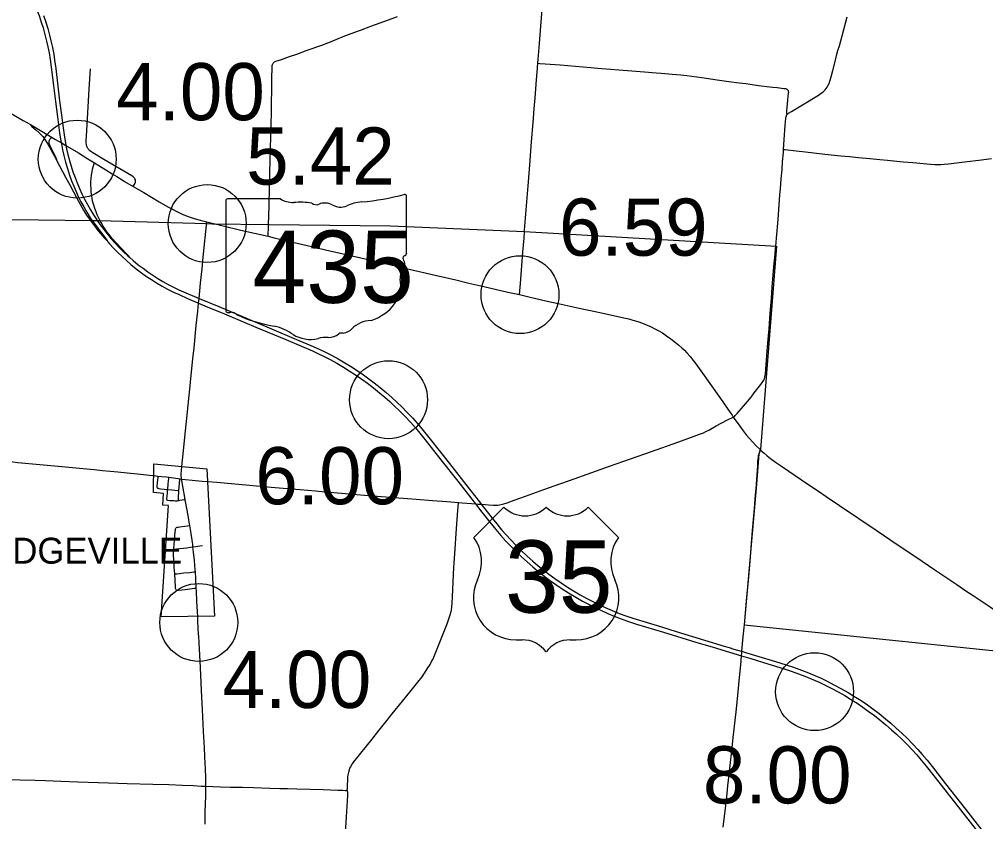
# Model space of a CAD drawing. Extents: x 1597222 to 1925846, y 496284 to 911751.
# Drawn here: x 1658757 to 1677369, y 576766 to 592215 of the extents above; entities that cross this region are included whole.
import ezdxf

# ---------------------------------------------------------------- set-up
doc = ezdxf.new("R2010")
doc.units = 0
for name, color, linetype in [('Default', 7, 'Continuous'), ('GM_X_City_Street', 7, 'Continuous'), ('GM_X_Corporation', 7, 'Continuous'), ('GM_X_Corporation_Text', 7, 'Continuous'), ('GM_X_County_Road', 7, 'Continuous'), ('GM_X_Interchange_Ramps', 7, 'Continuous'), ('GM_X_State_Route', 7, 'Continuous'), ('GM_X_State_Shield', 7, 'Continuous'), ('GM_X_Township', 7, 'Continuous'), ('GM_X_Township_Road', 7, 'Continuous'), ('GM_X_US_Route', 7, 'Continuous'), ('GM_X_US_Shield', 7, 'Continuous')]:
    doc.layers.add(name, color=color, linetype=linetype)

msp = doc.modelspace()

# ---------------------------------------------------------------- linework, layer by layer
at = {"layer": 'Default'}
for centre in [(1659873, 589523), (1659873, 589523), (1662376, 588283), (1662376, 588283), (1668401, 586914), (1668401, 586914), (1665868, 584891), (1665868, 584891), (1662214, 580602), (1662214, 580602), (1674074, 579269)]:
    msp.add_circle(centre, 750, dxfattribs=at)
at = {"layer": 'GM_X_City_Street'}
for points in [[(1661351, 583429), (1661427, 583421)], [(1661427, 583421), (1661424, 583393), (1661414, 583296), (1661405, 583215), (1661407, 583207), (1661409, 583200), (1661414, 583193), (1661420, 583189), (1661430, 583185), (1661441, 583182), (1661475, 583177), (1661548, 583171), (1661616, 583164)], [(1661427, 583421), (1661496, 583414), (1661592, 583405), (1661635, 583399)], [(1661616, 583164), (1661626, 583271), (1661634, 583373), (1661635, 583399)], [(1661635, 583399), (1661769, 583383), (1661817, 583376), (1661848, 583370)], [(1661832, 583144), (1661847, 583350), (1661848, 583370)], [(1661848, 583370), (1661883, 583364)], [(1661883, 583364), (1661953, 583356), (1662084, 583342), (1662281, 583325), (1662385, 583316)], [(1661820, 582944), (1661804, 582942), (1661794, 582940), (1661780, 582939), (1661760, 582939), (1661732, 582941), (1661698, 582944), (1661657, 582947), (1661614, 582952), (1661610, 582954), (1661607, 582956), (1661604, 582959), (1661602, 582962), (1661600, 582967), (1661599, 582970), (1661598, 582975), (1661598, 582978), (1661604, 583040), (1661609, 583092), (1661614, 583141), (1661616, 583164)], [(1661616, 583164), (1661694, 583156), (1661807, 583146), (1661832, 583144)], [(1661820, 582944), (1661820, 582960), (1661821, 582970), (1661824, 583016), (1661831, 583124), (1661832, 583144)], [(1661952, 582965), (1661926, 582961), (1661893, 582956), (1661845, 582948), (1661820, 582944)], [(1661732, 582013), (1661733, 582027), (1661752, 582256), (1661754, 582288), (1661764, 582386), (1661768, 582402), (1661774, 582417), (1661785, 582429), (1661800, 582436), (1661816, 582439), (1661849, 582443), (1661946, 582456), (1661995, 582463), (1662041, 582470)], [(1661750, 581536), (1661740, 581667), (1661731, 581814), (1661726, 581896), (1661727, 581945), (1661731, 581994), (1661732, 582013)], [(1661732, 582013), (1661783, 582018), (1661984, 582041), (1662056, 582049), (1662102, 582056)], [(1662102, 582056), (1662156, 582064), (1662237, 582075), (1662286, 582081)], [(1661750, 581536), (1661780, 581539), (1661796, 581540), (1661925, 581555), (1662039, 581567), (1662119, 581575), (1662149, 581579)], [(1662165, 581257), (1662133, 581253), (1661954, 581233), (1661889, 581226), (1661824, 581218), (1661807, 581217), (1661791, 581220), (1661777, 581228), (1661769, 581242), (1661765, 581258), (1661763, 581291), (1661750, 581536)]]:
    msp.add_lwpolyline(points, dxfattribs=at)
at = {"layer": 'GM_X_Corporation'}
msp.add_lwpolyline([(1661348, 583658), (1662369, 583561), (1662517, 580722), (1661488, 580713), (1661631, 582852), (1661519, 582859), (1661531, 583087), (1661343, 583102)], close=True, dxfattribs=at)
at = {"layer": 'GM_X_County_Road'}
for points in [[(1673543, 590381), (1673551, 590389), (1673561, 590398), (1673574, 590408), (1673631, 590442), (1673841, 590569), (1674149, 590757), (1674204, 590793), (1674230, 590812), (1674254, 590834), (1674277, 590857), (1674297, 590882), (1674315, 590909), (1674331, 590937), (1674352, 590981), (1674369, 591027), (1674391, 591105), (1674424, 591232), (1674481, 591455), (1674498, 591518), (1674525, 591613), (1674552, 591707), (1674605, 591897), (1674704, 592261)], [(1673477, 589710), (1673491, 589899), (1673503, 590079), (1673510, 590177), (1673515, 590242), (1673520, 590308), (1673521, 590325), (1673525, 590341), (1673530, 590358), (1673535, 590369), (1673543, 590381)], [(1673326, 587848), (1673339, 588003), (1673370, 588363), (1673391, 588641), (1673407, 588837), (1673417, 588951), (1673433, 589147), (1673447, 589327), (1673459, 589474), (1673473, 589654), (1673477, 589710)], [(1673477, 589710), (1673508, 589707), (1673718, 589682), (1673897, 589662), (1674272, 589620), (1674582, 589588), (1674663, 589579), (1674744, 589572), (1674923, 589555), (1675135, 589535), (1675331, 589518), (1675478, 589504), (1675657, 589486), (1675787, 589473), (1675967, 589457), (1676309, 589426), (1676391, 589419), (1676440, 589418), (1676506, 589420), (1676572, 589424), (1676653, 589433), (1677011, 589478), (1677239, 589505), (1677483, 589534)], [(1673117, 585324), (1673123, 585356), (1673127, 585388), (1673148, 585650), (1673163, 585830), (1673187, 586124), (1673198, 586254), (1673206, 586352), (1673215, 586467), (1673226, 586630), (1673242, 586843), (1673260, 587055), (1673292, 587448), (1673314, 587693), (1673323, 587811), (1673326, 587848)], [(1668393, 586915), (1668573, 586871), (1668925, 586789), (1669133, 586744), (1669598, 586644), (1669759, 586610), (1670031, 586550), (1670400, 586469), (1670495, 586446), (1670574, 586424), (1670668, 586395), (1670760, 586362), (1670852, 586326), (1670927, 586294), (1671000, 586258), (1671072, 586218), (1671142, 586176), (1671224, 586121), (1671304, 586064), (1671395, 585995), (1671458, 585943), (1671519, 585888), (1671566, 585842), (1671611, 585795), (1671676, 585721), (1671738, 585646), (1671788, 585581), (1671884, 585448), (1672054, 585206), (1672262, 584912), (1672450, 584642), (1672486, 584592), (1672509, 584558)], [(1672509, 584558), (1672530, 584571), (1672546, 584585), (1672585, 584625), (1672706, 584765), (1672783, 584858), (1672851, 584942), (1672913, 585023), (1672990, 585123), (1673036, 585182), (1673066, 585221), (1673086, 585251), (1673094, 585265), (1673108, 585294), (1673117, 585324)], [(1667214, 582912), (1667286, 582907), (1667465, 582892), (1667542, 582886), (1667597, 582882), (1667655, 582878), (1667727, 582872), (1667792, 582867), (1667891, 582862), (1667941, 582861), (1667974, 582862), (1668007, 582866), (1668039, 582872), (1668087, 582885), (1668150, 582905), (1668289, 582954), (1668505, 583033), (1668860, 583159), (1669169, 583269), (1669354, 583335), (1669787, 583489), (1670127, 583609), (1670529, 583750), (1670931, 583893), (1671441, 584074), (1671703, 584170), (1671857, 584226), (1671933, 584256), (1671978, 584277), (1672037, 584307), (1672181, 584385), (1672398, 584501), (1672509, 584558)], [(1672509, 584558), (1672541, 584513), (1672601, 584428), (1672698, 584295), (1672758, 584217), (1672821, 584142), (1672876, 584080), (1672945, 584009), (1673027, 583930), (1673029, 583928)], [(1656846, 583945), (1656933, 583938), (1657439, 583898), (1657717, 583874), (1657814, 583863), (1657895, 583851), (1657992, 583831), (1658264, 583770), (1658472, 583725), (1658552, 583710), (1658633, 583697), (1658731, 583685), (1659579, 583605), (1659987, 583565), (1660199, 583545), (1660362, 583530), (1660656, 583500), (1660835, 583483), (1661031, 583462), (1661324, 583432), (1661351, 583429)], [(1672802, 581413), (1672814, 581553), (1672832, 581782), (1672845, 581946), (1672859, 582126), (1672879, 582371), (1672916, 582796), (1672938, 583057), (1672948, 583172), (1672962, 583351), (1672974, 583534), (1672979, 583616), (1672983, 583699), (1672986, 583746), (1672991, 583782), (1672997, 583815), (1673006, 583851), (1673018, 583890), (1673029, 583928)], [(1673029, 583928), (1673100, 583863), (1673163, 583810), (1673227, 583759), (1673320, 583691), (1673454, 583596), (1673943, 583265), (1674148, 583129), (1674297, 583028), (1674556, 582853), (1675277, 582368), (1675684, 582092), (1676024, 581863), (1676392, 581615), (1676813, 581331), (1676990, 581211), (1677126, 581120), (1677453, 580900), (1677630, 580782), (1677766, 580690), (1678105, 580460), (1678419, 580251), (1678704, 580058), (1678915, 579914)], [(1662385, 583316), (1662559, 583301)], [(1662559, 583301), (1662908, 583271), (1663610, 583209), (1663839, 583189), (1664165, 583159), (1664459, 583134), (1664639, 583119), (1664739, 583110), (1664883, 583097), (1665112, 583076), (1665406, 583051), (1665815, 583018), (1666403, 582973), (1666714, 582949), (1666992, 582929), (1667214, 582912)], [(1672722, 580557), (1672772, 581096), (1672795, 581341), (1672802, 581413)], [(1672315, 576658), (1672326, 576772), (1672350, 576968), (1672381, 577245), (1672403, 577457), (1672433, 577734), (1672460, 577962), (1672478, 578125), (1672507, 578386), (1672544, 578712), (1672569, 578941), (1672596, 579202), (1672629, 579544), (1672651, 579789), (1672667, 579959), (1672672, 580018), (1672675, 580047), (1672695, 580263), (1672718, 580508), (1672722, 580557)], [(1658375, 577587), (1658769, 577573), (1659064, 577564), (1659261, 577557), (1659556, 577547), (1659884, 577536), (1660474, 577516), (1660835, 577504), (1661327, 577488), (1661638, 577479), (1661900, 577469), (1662114, 577461), (1662261, 577453), (1662338, 577448), (1662351, 577447)], [(1662351, 577447), (1662482, 577444), (1662629, 577439), (1662826, 577433), (1663055, 577428), (1663268, 577422), (1663580, 577413), (1663777, 577406), (1663924, 577403), (1664104, 577399), (1664612, 577384), (1664892, 577374), (1664990, 577371), (1665034, 577368), (1665073, 577366)], [(1665073, 577366), (1665075, 577330), (1665077, 577306), (1665079, 577273), (1665054, 576858), (1665019, 576335)]]:
    msp.add_lwpolyline(points, dxfattribs=at)
at = {"layer": 'GM_X_Interchange_Ramps'}
for points in [[(1658970, 590188), (1658980, 590172), (1658987, 590162), (1658996, 590150), (1659041, 590115), (1659077, 590086), (1659139, 590030), (1659174, 589995), (1659207, 589958), (1659237, 589920), (1659274, 589866), (1659309, 589810), (1659364, 589710), (1659472, 589508), (1659476, 589501), (1659649, 589176), (1659735, 589018), (1659865, 588772), (1659928, 588657), (1659994, 588544), (1660054, 588447), (1660109, 588366), (1660126, 588343), (1660140, 588325), (1660203, 588239), (1660271, 588150), (1660358, 588049), (1660400, 588000), (1660417, 587983), (1660435, 587966), (1660447, 587956)], [(1659392, 589942), (1659373, 589928), (1659359, 589919), (1659347, 589908), (1659337, 589895), (1659329, 589881), (1659325, 589865), (1659324, 589849), (1659327, 589833), (1659332, 589817), (1659345, 589788), (1659463, 589548), (1659476, 589518), (1659477, 589510), (1659476, 589501)], [(1660883, 587631), (1660882, 587634), (1660879, 587638), (1660857, 587663), (1660820, 587702), (1660623, 587910), (1660547, 587996), (1660485, 588072), (1660445, 588124), (1660408, 588177), (1660373, 588233), (1660333, 588304), (1660314, 588338), (1660294, 588376), (1660259, 588450), (1660234, 588510), (1660211, 588572), (1660192, 588634), (1660175, 588697), (1660161, 588761), (1660151, 588826), (1660143, 588890), (1660138, 588956), (1660136, 589021), (1660137, 589086), (1660141, 589152), (1660148, 589217), (1660159, 589281), (1660169, 589329), (1660181, 589377), (1660186, 589392), (1660206, 589452)]]:
    msp.add_lwpolyline(points, dxfattribs=at)
at = {"layer": 'GM_X_State_Route'}
for points in [[(1668393, 586915), (1668411, 587126), (1668458, 587731), (1668478, 587999), (1668488, 588129), (1668490, 588156), (1668508, 588385), (1668521, 588548), (1668537, 588777), (1668562, 589088), (1668587, 589415), (1668622, 589856), (1668652, 590232), (1668674, 590494), (1668690, 590706), (1668716, 591050), (1668728, 591197), (1668742, 591371), (1668748, 591442), (1668774, 591753), (1668794, 591998), (1668841, 592570)], [(1658299, 590586), (1658313, 590577), (1658500, 590462), (1658646, 590376), (1658832, 590268), (1658970, 590188)], [(1658970, 590188), (1659231, 590037), (1659392, 589942), (1659457, 589903), (1659501, 589877)], [(1659501, 589877), (1659563, 589841), (1659656, 589785), (1659683, 589769), (1659896, 589643), (1660078, 589531), (1660206, 589452)], [(1660206, 589452), (1660287, 589402), (1660421, 589317), (1660547, 589239), (1660635, 589186), (1660755, 589113)], [(1660755, 589113), (1660786, 589094), (1660950, 588998), (1661153, 588878), (1661449, 588703), (1661619, 588604), (1661706, 588557), (1661794, 588513), (1661883, 588473), (1661989, 588428), (1662066, 588399), (1662144, 588374), (1662239, 588346), (1662370, 588315)], [(1662203, 586676), (1662211, 586752), (1662220, 586842), (1662249, 587133), (1662277, 587410), (1662300, 587639), (1662370, 588315)], [(1662370, 588315), (1662657, 588245), (1663024, 588158), (1663551, 588037), (1663664, 588011), (1663967, 587939), (1664382, 587843), (1664654, 587779), (1665532, 587576), (1666267, 587405), (1666682, 587309), (1667162, 587198), (1667417, 587138), (1667705, 587072), (1668168, 586964), (1668393, 586915)], [(1662062, 585299), (1662100, 585681), (1662122, 585893), (1662165, 586317), (1662194, 586594), (1662203, 586676)], [(1661890, 583607), (1661915, 583852), (1661960, 584293), (1661984, 584538), (1662010, 584783), (1662055, 585223), (1662062, 585299)], [(1662167, 581215), (1662165, 581257), (1662156, 581450), (1662149, 581579), (1662147, 581614), (1662131, 581793), (1662114, 581957), (1662102, 582056), (1662097, 582103), (1662065, 582314), (1662041, 582470), (1662038, 582493), (1662016, 582622), (1661989, 582767), (1661952, 582965), (1661943, 583009), (1661913, 583187), (1661887, 583333), (1661883, 583364), (1661880, 583382), (1661877, 583432), (1661877, 583465), (1661881, 583531), (1661890, 583607)], [(1662193, 580718), (1662177, 581007), (1662167, 581204), (1662167, 581215)], [(1662197, 580629), (1662193, 580718)], [(1662335, 576718), (1662339, 576964), (1662347, 577259), (1662351, 577423), (1662351, 577447), (1662352, 577488), (1662349, 577619), (1662342, 577783), (1662330, 578012), (1662321, 578192), (1662306, 578504), (1662284, 578929), (1662265, 579290), (1662244, 579732), (1662220, 580207), (1662213, 580338), (1662211, 580371), (1662197, 580629)]]:
    msp.add_lwpolyline(points, dxfattribs=at)
at = {"layer": 'GM_X_State_Shield'}
for p, q in [((1662734, 588720), (1662734, 586607)), ((1663787, 588757), (1662768, 588757)), ((1666214, 587703), (1666214, 588809)), ((1666214, 587704), (1666214, 587703))]:
    msp.add_line(p, q, dxfattribs=at)
for centre, major_axis, start_param, end_param in [((1662774, 588725), (40.3, 0), 1.712693, 3.28349), ((1664030, 589002), (391, 0), 4.042523, 4.731795), ((1665445, 588111), (743, 0), 1.699011, 2.107814), ((1664974, 591638), (3691, 0), 4.814394, 5.042369), ((1666176, 588814), (38.7, 0), 6.141152, 7.989035), ((1664160, 587570), (1404, 0), 1.404758, 1.657858), ((1664478, 588736), (113, 0), 3.836095, 5.185415), ((1664644, 588491), (235, 0), 0.950623, 2.079405), ((1664947, 588826), (282, 0), 4.081561, 5.145723), ((1666205, 587622), (60, 0), 1.883978, 3.671073), ((1665824, 587483), (360, 0), 5.934695, 6.695948), ((1666173, 587699), (41.5, 0), 5.05454, 6.418171), ((1665181, 587100), (923, 0), 5.101752, 6.440018), ((1666353, 587241), (262, 0), 2.387724, 3.262537), ((1662774, 586602), (40.7, 0), 3.00124, 4.508301), ((1662780, 586819), (310, 0), 4.665946, 4.897461), ((1662844, 586485), (112, 0), 0.519207, 1.627899), ((1664257, 588384), (2665, 0), 4.195997, 4.488961), ((1663462, 585658), (834, 0), 0.823519, 1.323587), ((1665570, 586014), (506, 0), 1.647645, 2.488434), ((1664364, 586475), (529, 0), 4.026481, 4.996735), ((1664670, 585744), (435, 0), 1.495662, 1.94098), ((1664709, 586316), (282, 0), 4.691044, 5.507374), ((1664964, 586112), (79.4, 0), 1.147584, 2.315152), ((1664930, 586402), (298, 0), 4.937069, 5.64225)]:
    msp.add_ellipse(centre, major_axis=major_axis, ratio=0.8, start_param=start_param, end_param=end_param, dxfattribs=at)
at = {"layer": 'GM_X_Township'}
msp.add_lwpolyline([(1640772, 591419), (1641501, 591232), (1645959, 590087), (1646099, 590051), (1651332, 588679), (1652031, 588630), (1654972, 588478), (1658610, 588362), (1660153, 588344), (1660296, 588340), (1662371, 588281), (1662472, 588280), (1663570, 588267), (1665903, 588241), (1668490, 588131), (1673343, 587846), (1673034, 583935), (1673000, 583850), (1672955, 583266), (1672719, 580558), (1678923, 579915)], dxfattribs=at)
at = {"layer": 'GM_X_Township_Road'}
for points in [[(1663558, 588266), (1663564, 588427), (1663569, 588640), (1663578, 588967), (1663585, 589279), (1663590, 589476), (1663597, 589722), (1663602, 589968), (1663607, 590214), (1663611, 590394), (1663616, 590623), (1663619, 590837), (1663623, 591083), (1663624, 591279), (1663626, 591312), (1663628, 591329), (1663631, 591345), (1663637, 591360), (1663645, 591374), (1663656, 591385), (1663669, 591394), (1663683, 591402), (1663699, 591408), (1663808, 591445), (1663963, 591499), (1664102, 591547), (1664303, 591619), (1664581, 591719), (1664719, 591772), (1664871, 591833), (1664993, 591882), (1665146, 591940), (1665330, 592009), (1665530, 592083), (1665869, 592206), (1666039, 592267)], [(1668742, 591371), (1668784, 591368), (1668882, 591360), (1669176, 591338), (1669618, 591300), (1669765, 591288), (1669896, 591278), (1670059, 591264), (1670386, 591238), (1670795, 591204), (1671024, 591185), (1671122, 591178), (1671334, 591159), (1671498, 591145), (1671612, 591134), (1671710, 591122), (1671905, 591094), (1672197, 591051), (1672424, 591020), (1672619, 590993), (1672750, 590977), (1672993, 590944), (1673156, 590924), (1673270, 590911), (1673352, 590902), (1673483, 590886), (1673499, 590884), (1673515, 590881), (1673524, 590878), (1673532, 590876), (1673539, 590873), (1673547, 590867), (1673554, 590861), (1673559, 590855), (1673563, 590847), (1673566, 590839), (1673568, 590831), (1673569, 590821), (1673569, 590809), (1673567, 590794), (1673562, 590739), (1673555, 590657), (1673535, 590444), (1673534, 590411), (1673535, 590399), (1673538, 590391), (1673543, 590381)], [(1660950, 588998), (1660969, 589031), (1660986, 589060), (1660992, 589076), (1660995, 589093), (1660995, 589110), (1660992, 589127), (1660985, 589144), (1660976, 589158), (1660965, 589170), (1660952, 589182), (1660924, 589201), (1660385, 589517), (1660173, 589643), (1660132, 589670), (1660108, 589691), (1660097, 589702), (1660087, 589715), (1660078, 589728), (1660070, 589742), (1660063, 589756), (1660057, 589771), (1660053, 589787), (1660049, 589802), (1660046, 589835), (1660046, 589883), (1660050, 589965), (1660102, 590868), (1660127, 591262)], [(1663551, 588037), (1663552, 588082), (1663556, 588190), (1663558, 588266)], [(1665073, 577366), (1665074, 577384), (1665076, 577407), (1665077, 577427), (1665078, 577457), (1665083, 577570), (1665086, 577620), (1665092, 577668), (1665101, 577717), (1665115, 577764), (1665126, 577795), (1665139, 577825), (1665155, 577853), (1665173, 577881), (1665202, 577921), (1665551, 578355), (1665663, 578496), (1665815, 578690), (1665938, 578843), (1666135, 579084), (1666279, 579263), (1666433, 579455), (1666513, 579558), (1666561, 579625), (1666615, 579707), (1666667, 579791), (1666698, 579848), (1666719, 579892), (1666751, 579968), (1666893, 580317), (1666995, 580576), (1667029, 580669), (1667055, 580747), (1667073, 580810), (1667079, 580836), (1667083, 580858), (1667087, 580882), (1667090, 580906), (1667095, 580972), (1667101, 581103), (1667128, 581659), (1667143, 581921), (1667178, 582411), (1667204, 582755), (1667214, 582905), (1667214, 582912)]]:
    msp.add_lwpolyline(points, dxfattribs=at)
at = {"layer": 'GM_X_US_Route'}
for points in [[(1658732, 593127), (1658799, 593014), (1658863, 592900), (1658917, 592798), (1658953, 592724), (1658995, 592635), (1659041, 592530), (1659091, 592408), (1659138, 592286), (1659181, 592161), (1659215, 592052), (1659250, 591925), (1659282, 591798), (1659307, 591686), (1659330, 591573), (1659351, 591443), (1659372, 591297), (1659417, 590939), (1659456, 590630), (1659493, 590337), (1659533, 590028), (1659545, 589947), (1659556, 589879)], [(1659225, 592286), (1659266, 592162), (1659305, 592037), (1659340, 591910), (1659367, 591799), (1659395, 591671), (1659419, 591542), (1659437, 591429), (1659459, 591266), (1659533, 590648), (1659569, 590371), (1659602, 590127), (1659627, 589948), (1659646, 589835), (1659656, 589785), (1659668, 589722), (1659694, 589610), (1659723, 589499), (1659755, 589389), (1659791, 589279), (1659830, 589171), (1659871, 589064), (1659916, 588958), (1659964, 588854), (1660015, 588750), (1660069, 588649), (1660126, 588549), (1660186, 588451), (1660249, 588355), (1660259, 588340), (1660315, 588261), (1660383, 588168), (1660454, 588078), (1660528, 587990), (1660604, 587904), (1660683, 587820), (1660764, 587739), (1660849, 587661), (1660883, 587631), (1660948, 587574), (1661049, 587491), (1661140, 587421), (1661233, 587353), (1661328, 587289), (1661426, 587227), (1661524, 587168), (1661625, 587112), (1661727, 587060), (1661831, 587010), (1661966, 586950), (1662177, 586860), (1662220, 586842), (1662601, 586683), (1663568, 586276), (1664143, 586034), (1664369, 585937), (1664533, 585863), (1664651, 585806), (1664768, 585746), (1664898, 585676), (1665025, 585602), (1665137, 585534), (1665261, 585454), (1665383, 585371), (1665489, 585294), (1665594, 585215), (1665710, 585124), (1665823, 585030), (1665934, 584933), (1666031, 584844), (1666125, 584753), (1666229, 584648), (1666330, 584540), (1666417, 584442), (1666512, 584330), (1666646, 584164), (1666869, 583881), (1667041, 583661), (1667354, 583260), (1667618, 582925), (1667655, 582878), (1667840, 582641), (1667953, 582500), (1668047, 582386), (1668133, 582287), (1668221, 582190), (1668313, 582095), (1668417, 581991), (1668537, 581878), (1668647, 581780), (1668747, 581695), (1668837, 581623), (1668954, 581533), (1669073, 581446), (1669194, 581362), (1669318, 581281), (1669430, 581212), (1669557, 581137), (1669686, 581065), (1669803, 581004), (1669920, 580946), (1670040, 580891), (1670175, 580832), (1670312, 580777), (1670436, 580732), (1670575, 580684), (1670763, 580624), (1671124, 580515), (1671407, 580429), (1671956, 580263), (1672332, 580145), (1672426, 580117), (1672521, 580090), (1672663, 580050), (1672675, 580047), (1672741, 580026), (1673321, 579850), (1673525, 579787), (1673665, 579740), (1673819, 579685), (1673957, 579631), (1674078, 579581), (1674198, 579528), (1674316, 579471), (1674447, 579404), (1674592, 579327), (1674720, 579254), (1674832, 579185), (1674970, 579097), (1675092, 579014), (1675198, 578937), (1675315, 578848), (1675443, 578746), (1675544, 578662), (1675642, 578575), (1675763, 578464), (1675857, 578372), (1675960, 578267), (1676060, 578159), (1676147, 578061), (1676242, 577948), (1676366, 577795), (1676598, 577497), (1676981, 577006), (1677293, 576604)], [(1659556, 589879), (1659563, 589841), (1659567, 589818), (1659589, 589705), (1659615, 589594), (1659648, 589467), (1659685, 589341), (1659725, 589216), (1659764, 589108), (1659805, 589001), (1659843, 588911), (1659892, 588807), (1659943, 588704), (1659998, 588603), (1660056, 588504), (1660124, 588393), (1660159, 588342), (1660174, 588321), (1660389, 588031), (1660447, 587956), (1660463, 587934), (1660495, 587895), (1660573, 587811), (1660653, 587728), (1660735, 587648), (1660819, 587571), (1660906, 587496), (1661008, 587413), (1661112, 587333), (1661205, 587266), (1661300, 587203), (1661398, 587142), (1661511, 587076), (1661612, 587021), (1661729, 586962), (1661833, 586914), (1661999, 586843), (1662165, 586772), (1662191, 586761)], [(1662191, 586761), (1662211, 586752), (1662376, 586681), (1662709, 586543), (1663103, 586378), (1663314, 586289), (1663889, 586048), (1664192, 585921), (1664403, 585830), (1664508, 585783), (1664626, 585725), (1664742, 585664), (1664872, 585593), (1665000, 585519), (1665111, 585450), (1665235, 585369), (1665357, 585286), (1665463, 585209), (1665581, 585119), (1665696, 585026), (1665796, 584942), (1665895, 584854), (1665979, 584776), (1666085, 584673), (1666188, 584568), (1666289, 584459), (1666387, 584349), (1666471, 584248), (1666574, 584120), (1666877, 583732), (1667202, 583320), (1667516, 582920), (1667542, 582886), (1667668, 582726), (1667819, 582532), (1667933, 582392), (1668028, 582279), (1668127, 582170), (1668228, 582062), (1668320, 581969), (1668427, 581867), (1668536, 581767), (1668647, 581671), (1668735, 581598), (1668851, 581506), (1668969, 581417), (1669089, 581332), (1669212, 581250), (1669336, 581171), (1669477, 581087), (1669605, 581014), (1669721, 580952), (1669853, 580886), (1669971, 580830), (1670091, 580776), (1670212, 580726), (1670350, 580673), (1670489, 580623), (1670645, 580572), (1671162, 580413), (1671790, 580224), (1672120, 580124), (1672434, 580029), (1672667, 579959), (1672843, 579905), (1673172, 579805), (1673486, 579709), (1673642, 579658), (1673766, 579614), (1673888, 579567), (1674010, 579517), (1674160, 579450), (1674279, 579395), (1674396, 579335), (1674527, 579265), (1674655, 579193), (1674768, 579125), (1674893, 579046), (1675002, 578973), (1675109, 578897), (1675228, 578809), (1675331, 578727), (1675445, 578634), (1675557, 578537), (1675654, 578449), (1675762, 578347), (1675866, 578243), (1675956, 578147), (1676044, 578050), (1676130, 577950), (1676224, 577836), (1676396, 577616), (1676628, 577319), (1677325, 576427)]]:
    msp.add_lwpolyline(points, dxfattribs=at)
at = {"layer": 'GM_X_US_Shield'}
for p, q in [((1668092, 582821), (1667512, 582240)), ((1670296, 582240), (1669716, 582821)), ((1668324, 580268), (1668440, 580268)), ((1669368, 580268), (1669484, 580268))]:
    msp.add_line(p, q, dxfattribs=at)
for centre, radius, start, end in [((1668498, 583235), 580, 225.573, 314.427), ((1669310, 583235), 580, 225.573, 314.427), ((1666847, 581775), 812, 334.5471, 35.0009), ((1670962, 581775), 812, 144.9991, 205.4529), ((1668315, 581080), 812, 154.8319, 270.6383), ((1669493, 581080), 812, 269.3617, 25.1681), ((1668440, 579688), 580, 36.8699, 90), ((1669368, 579688), 580, 90, 143.1301)]:
    msp.add_arc(centre, radius, start, end, dxfattribs=at)

# ---------------------------------------------------------------- texts
at = {"layer": 'Default'}
for s, p in [('4.00', (1660623, 590273)), ('4.00', (1660623, 590273)), ('5.42', (1663126, 589033)), ('5.42', (1663126, 589033)), ('6.59', (1669151, 587664)), ('6.59', (1669151, 587664)), ('6.00', (1663303, 582878)), ('6.00', (1663303, 582878)), ('4.00', (1662673, 578955)), ('8.00', (1671923, 577118))]:
    msp.add_text(s, height=1100, dxfattribs=at).set_placement(p)
at = {"layer": 'GM_X_Corporation_Text'}
msp.add_text('MILLEDGEVILLE', height=500, rotation=0, dxfattribs=at).set_placement((1656690, 581734))
at = {"layer": 'GM_X_State_Shield'}
msp.add_text('435', height=1392.2, dxfattribs=at).set_placement((1663248, 586756))
at = {"layer": 'GM_X_US_Shield'}
msp.add_text('35', height=1392.2, dxfattribs=at).set_placement((1668112, 580790))

doc.saveas('drawing.dxf')
